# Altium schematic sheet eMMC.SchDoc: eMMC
size A4; Date: Not used; ApprovedBy: Not used; CheckedBy: Not used; Author: Not used; CompanyName: STMicroelectronics; DrawnBy: Not used; Engineer: Not used; Organization: Not used; Address1: Not used; Address2: Not used; Address3: Not used; Address4: Not used; DocumentNumber: Not used; Revision: Not used; SheetNumber: 8; SheetTotal: 16
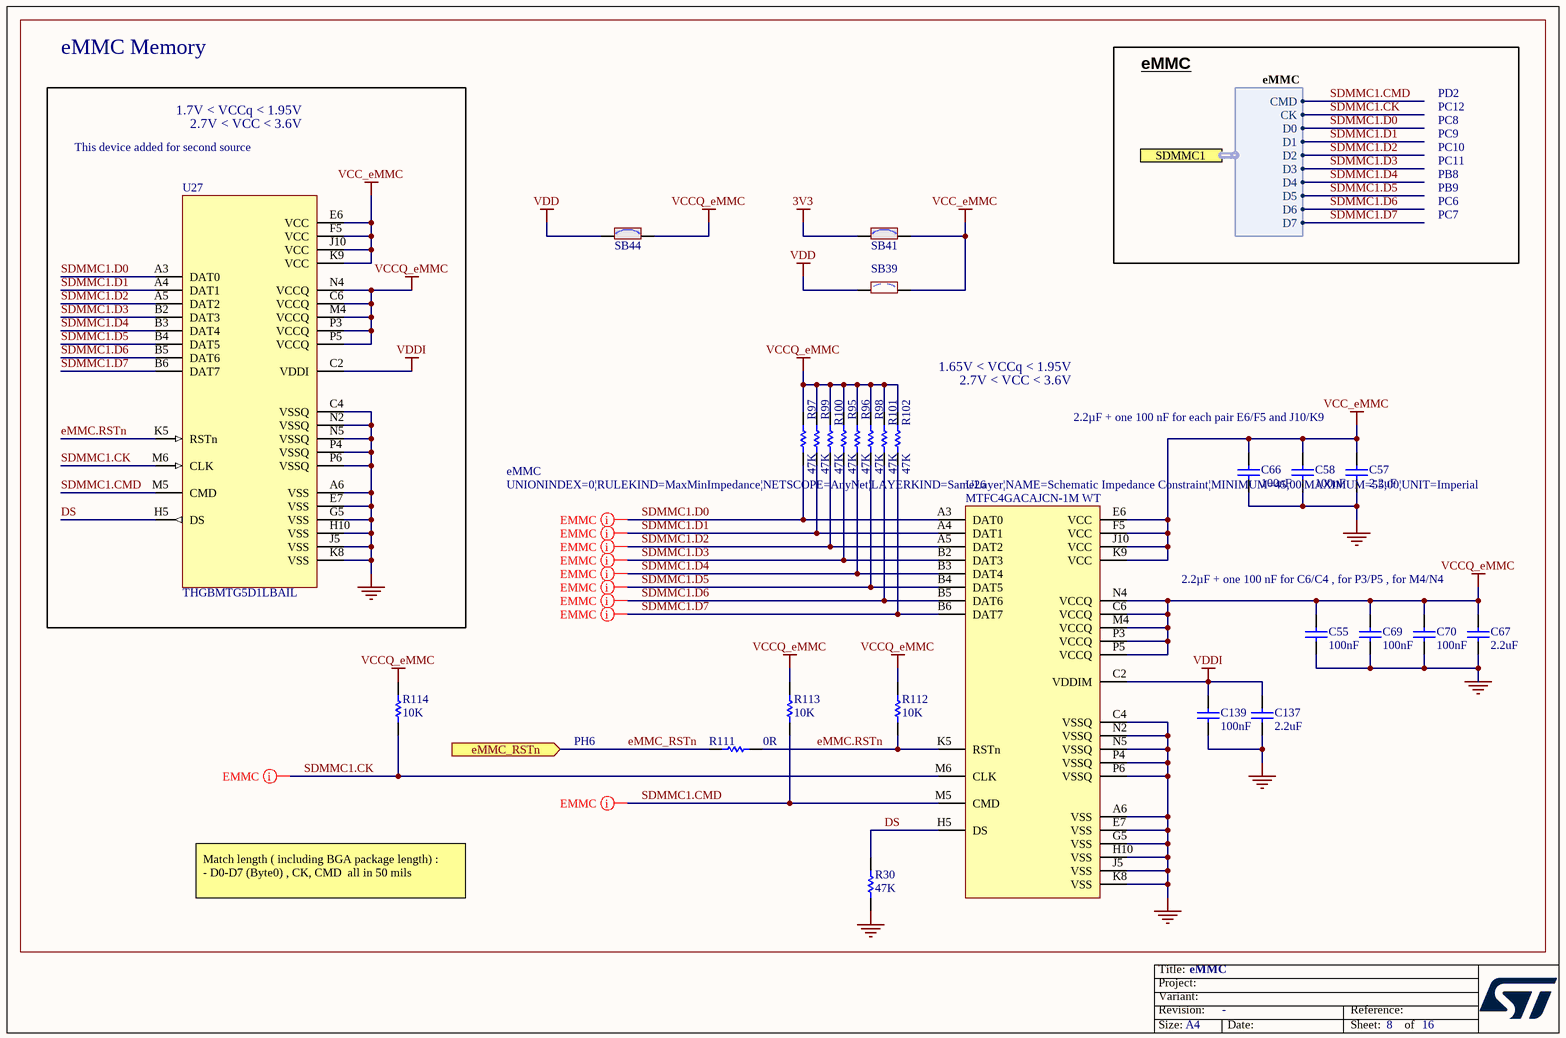
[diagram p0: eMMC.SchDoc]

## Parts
C55  value 100nF  [C0402]  (hidden comment: Capacitor)
C57  value 2.2uF  [C0603]  (hidden comment: Capacitor)
C58  value 100nF  [C0402]  (hidden comment: Capacitor)
C66  value 100nF  [C0402]  (hidden comment: Capacitor)
C67  value 2.2uF  [C0603]  (hidden comment: Capacitor)
C69  value 100nF  [C0402]  (hidden comment: Capacitor)
C70  value 100nF  [C0402]  (hidden comment: Capacitor)
C137  value 2.2uF  [C0603]  (hidden comment: Capacitor)
C139  value 100nF  [C0402]  (hidden comment: Capacitor)
R30  value 47K  [R0402]  (hidden comment: Resistor)
R95  value 47K  [R0402]  (hidden comment: Resistor)
R96  value 47K  [R0402]  (hidden comment: Resistor)
R97  value 47K  [R0402]  (hidden comment: Resistor)
R98  value 47K  [R0402]  (hidden comment: Resistor)
R99  value 47K  [R0402]  (hidden comment: Resistor)
R100  value 47K  [R0402]  (hidden comment: Resistor)
R101  value 47K  [R0402]  (hidden comment: Resistor)
R102  value 47K  [R0402]  (hidden comment: Resistor)
R111  value 0R  [R0402]  (hidden comment: Resistor)
R112  value 10K  [R0402]  (hidden comment: Resistor)
R113  value 10K  [R0402]  (hidden comment: Resistor)
R114  value 10K  [R0402]  (hidden comment: Resistor)
SB39  SB_OFF  [SOLDER-BRIDGE_R0402-0R]  (value not drawn)
SB41  SB_ON  [SOLDER-BRIDGE_R0402-0R]  (value not drawn)
SB44  SB_ON  [SOLDER-BRIDGE_R0402-0R]  (value not drawn)
U26  MTFC4GACAJCN-1M WT  [ICC_P-WFBGA153_13X11P5_P050]
U27  value THGBMTG5D1LBAIL  [ICC_P-WFBGA153_13X11P5_P050]  (hidden comment: eMMC_THGBMTG5D1LBAIL)

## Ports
eMMC_RSTn (in), SDMMC1 (harness eMMC)

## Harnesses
eMMC: D0, CMD, CK, D1, D2, D3, D4, D5, D6, D7

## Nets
3V3: SB41.1
GND: C55.1 C57.1 C58.1 C66.1 C67.1 C69.1 C70.1 C137.1 C139.1 R30.1 U26.A6(VSS) U26.C4(VSSQ) U26.E7(VSS) U26.G5(VSS) U26.H10(VSS) U26.J5(VSS) U26.K8(VSS) U26.N2(VSSQ) U26.N5(VSSQ) U26.P4(VSSQ) U26.P6(VSSQ) U27.A6(VSS) U27.C4(VSSQ) U27.E7(VSS) U27.G5(VSS) U27.H10(VSS) U27.J5(VSS) U27.K8(VSS) U27.N2(VSSQ) U27.N5(VSSQ) U27.P4(VSSQ) U27.P6(VSSQ)
VCC_eMMC: C57.2 C58.2 C66.2 SB39.2 SB41.2 U26.E6(VCC) U26.F5(VCC) U26.J10(VCC) U26.K9(VCC) U27.E6(VCC) U27.F5(VCC) U27.J10(VCC) U27.K9(VCC)
VCCQ_eMMC: C55.2 C67.2 C69.2 C70.2 R95.2 R96.2 R97.2 R98.2 R99.2 R100.2 R101.2 R102.2 R112.2 R113.2 R114.2 SB44.2 U26.C6(VCCQ) U26.M4(VCCQ) U26.N4(VCCQ) U26.P3(VCCQ) U26.P5(VCCQ) U27.C6(VCCQ) U27.M4(VCCQ) U27.N4(VCCQ) U27.P3(VCCQ) U27.P5(VCCQ)
VDD: SB39.1 SB44.1
VDDI: C137.2 C139.2 U26.C2(VDDIM) U27.C2(VDDI)
DS: R30.2 U26.H5(DS) U27.H5(DS)
eMMC.RSTn: R111.2 R112.1 U26.K5(RSTn) U27.K5(RSTn)
eMMC_RSTn: R111.1 ; port eMMC_RSTn
SDMMC1.CK: R114.1 U26.M6(CLK) U27.M6(CLK) ; port SDMMC1.CK
SDMMC1.CMD: R113.1 U26.M5(CMD) U27.M5(CMD) ; port SDMMC1.CMD
SDMMC1.D0: R97.1 U26.A3(DAT0) U27.A3(DAT0) ; port SDMMC1.D0
SDMMC1.D1: R99.1 U26.A4(DAT1) U27.A4(DAT1) ; port SDMMC1.D1
SDMMC1.D2: R100.1 U26.A5(DAT2) U27.A5(DAT2) ; port SDMMC1.D2
SDMMC1.D3: R95.1 U26.B2(DAT3) U27.B2(DAT3) ; port SDMMC1.D3
SDMMC1.D4: R96.1 U26.B3(DAT4) U27.B3(DAT4) ; port SDMMC1.D4
SDMMC1.D5: R98.1 U26.B4(DAT5) U27.B4(DAT5) ; port SDMMC1.D5
SDMMC1.D6: R101.1 U26.B5(DAT6) U27.B5(DAT6) ; port SDMMC1.D6
SDMMC1.D7: R102.1 U26.B6(DAT7) U27.B6(DAT7) ; port SDMMC1.D7

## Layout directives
rule Matched Net Lengths [Tolerance = 20mil]; rule Impedance Constraint [Min = 45.00    Max = 55.00    ]; net class eMMC: SDMMC1.D0
rule Matched Net Lengths [Tolerance = 20mil]; rule Impedance Constraint [Min = 45.00    Max = 55.00    ]: SDMMC1.CK, SDMMC1.D1, SDMMC1.D2, SDMMC1.D3, SDMMC1.D4, SDMMC1.D5, SDMMC1.D6, SDMMC1.D7
rule Matched Net Lengths [Tolerance = 50mil]; rule Impedance Constraint [Min = 45.00    Max = 55.00    ]: SDMMC1.CMD

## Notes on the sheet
- eMMC Memory
- 1.7V < VCCq < 1.95V
- 2.7V < VCC < 3.6V
- eMMC
- PC12
- PD2
- This device added for second source
- PC8
- PC9
- PC10
- PC11
- PB8
- PC6
- PC7
- PB9
- 1.65V < VCCq < 1.95V
- 2.2µF + one 100 nF for each pair E6/F5 and J10/K9
- 2.2µF + one 100 nF for C6/C4 , for P3/P5 , for M4/N4
- PH6
- Match length ( including BGA package length) :
  - D0-D7 (Byte0) , CK, CMD  all in 50 mils

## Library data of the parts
C55 C58 C66 C69 C70 C139 = MCD-00006: Capacitor, MLCC, 100nF, 16V, X7R, +/-10%, 0402, T=0.5mm; Manufacturer_Part_Number: CC0402KRX7R7BB104; Manufacturer: YAGEO; Part_Preference: Recommended; Order_Code_RS: 616-9701; Component_Country_Of_Origin: China
C57 C67 C137 = MCD-00012: Capacitor, MLCC, 2.2uF, 10V, X5R, +/- 10%, 0603, T=0.8mm; Manufacturer_Part_Number: CC0603KRX5R6BB225; Manufacturer: YAGEO; BMS_Part_Number: 9142010; Part_Preference: Recommended; Component_Country_Of_Origin: China
R30 R95-R102 = MCD-00063: Resistor, 47K, 0402, +/-1%, 1/16W; Manufacturer_Part_Number: RC0402FR-0747KL; Manufacturer: YAGEO; Part_Preference: Recommended; Component_Country_Of_Origin: China
R111 = MCD-00052: Resistor, 0R, 0402, +/-5%, 1/16W; Manufacturer_Part_Number: RC0402JR-070RL; Manufacturer: YAGEO; Part_Preference: Recommended; Order_Code_RS: 618-5804; Component_Country_Of_Origin: China
R112-R114 = MCD-00053: Resistor, 10K, 0402, +/-1%, 1/16W; Manufacturer_Part_Number: RC0402FR-0710KL; Manufacturer: YAGEO; BMS_Part_Number: 9131590; Part_Preference: Recommended; Component_Country_Of_Origin: China
SB39 = MCD-02162: Solder Bridge 0402 OFF; Part_Type: Misc; Manufacturer_Part_Number: RC0402JR-070RL; Manufacturer: YAGEO; Part_Preference: Recommended; Order_Code_RS: 618-5804; Component_Country_Of_Origin: China
SB41 SB44 = MCD-01618: Solder Bridge 0402 ON; Part_Type: Misc; Manufacturer_Part_Number: RC0402JR-070RL; Manufacturer: YAGEO; Part_Preference: Recommended; Order_Code_RS: 618-5804; Component_Country_Of_Origin: China
U26 = MCD-01137: 4G MultiMediaCard (MMC) controller and NAND Flash; Part_Type: IC; Manufacturer: MICRON; BMS_Part_Number: 9171977; Part_Preference: Recommended; Component_Country_Of_Origin: Singapore
U27 = MCD-02799: Memory, eMMC, 4GB, 15nm ,WFBGA , 153 pins; Part_Type: IC; Part_Preference: Recommended; Manufacturer: KIOXIA; Component_Country_Of_Origin: Unknown; ShowFields: YES; ID: 4911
